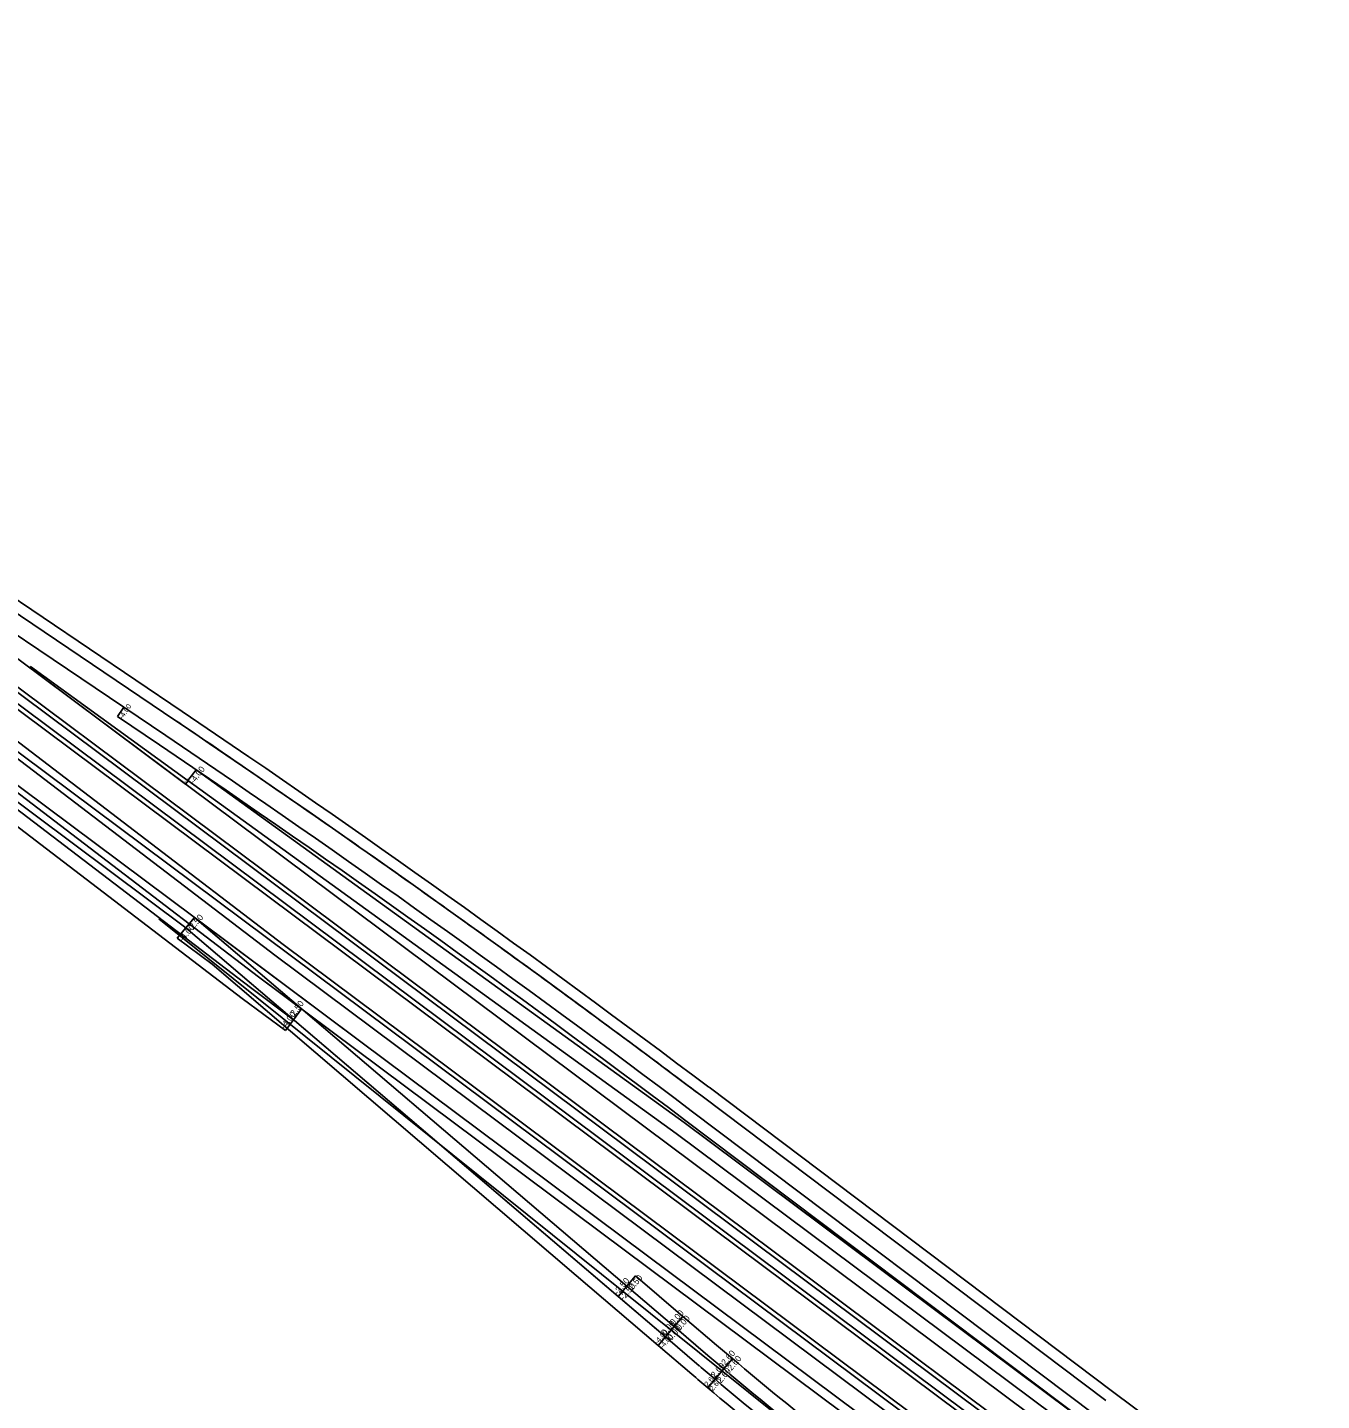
# Model space of a CAD drawing. Extents: x 2342222 to 2351711, y 366548 to 372860.
# Drawn here: x 2344214 to 2345363, y 370762 to 371981 of the extents above; entities that cross this region are included whole.
import ezdxf

# ---------------------------------------------------------------- set-up
doc = ezdxf.new("R2010")
doc.units = 0
for name, color, linetype in [('RD_PD_Final_LnLine', 7, 'Continuous'), ('RD_PD_PaveShd', 7, 'Continuous'), ('RD_PD_SuperShp_BL_EB_526', 7, 'Continuous'), ('RD_PD_SuperShp_BL_WB_526', 7, 'Continuous'), ('RD_PD_SuperShp_EB_526', 7, 'Continuous'), ('RD_PD_SuperShp_LINE-A', 7, 'Continuous'), ('RD_PD_SuperShp_REL_LINE-3', 7, 'Continuous'), ('RD_PD_SuperShp_WB_526', 7, 'Continuous')]:
    doc.layers.add(name, color=color, linetype=linetype)

msp = doc.modelspace()

# ---------------------------------------------------------------- linework, layer by layer
at = {"layer": 'RD_PD_Final_LnLine'}
msp.add_line((2344330.6, 371189.3), (2344989.7, 370660.6), dxfattribs=at)
msp.add_line((2344330.6, 371189.3), (2344989.7, 370660.6), dxfattribs=at)
at = {"layer": 'RD_PD_PaveShd'}
for p, q in [((2344136.5, 371426.7), (2345306.6, 370553.4)), ((2344363.7, 371321.8), (2344797.2, 371008.5)), ((2344797.2, 371008.5), (2345171.3, 370729.2))]:
    msp.add_line(p, q, dxfattribs=at)
at = {"layer": 'RD_PD_SuperShp_BL_EB_526'}
for p, q in [((2344441, 371166.6), (2343459.8, 371915.6)), ((2343465, 371896.5), (2344433.7, 371157)), ((2343853.9, 371599.7), (2344433.7, 371157)), ((2344419.3, 371137.9), (2343839.3, 371580.6)), ((2344419.3, 371137.9), (2343839.3, 371580.6)), ((2343832.1, 371571), (2344412.1, 371128.3)), ((2344412.1, 371128.3), (2343832.1, 371571)), ((2343824.8, 371561.5), (2344404.8, 371118.7)), ((2345290.9, 370532.3), (2344441, 371166.6)), ((2344433.7, 371157), (2345206.8, 370580.1)), ((2344433.7, 371157), (2345283.7, 370522.7)), ((2344412.1, 371128.3), (2344450.2, 371099.8)), ((2344450.2, 371099.8), (2344412.1, 371128.3)), ((2345192.4, 370560.9), (2344419.3, 371137.9)), ((2344457.4, 371109.4), (2344419.3, 371137.9)), ((2344404.8, 371118.7), (2344443, 371090.2)), ((2344450.2, 371099.8), (2344457.4, 371109.4)), ((2344443, 371090.2), (2344450.2, 371099.8))]:
    msp.add_line(p, q, dxfattribs=at)
at = {"layer": 'RD_PD_SuperShp_BL_WB_526'}
for p, q in [((2345328.2, 370582.3), (2344157.9, 371455.7)), ((2344143.6, 371436.4), (2345313.8, 370563)), ((2345236.9, 370620.4), (2344143.6, 371436.4)), ((2344136.5, 371426.7), (2345229.7, 370610.8)), ((2344216.6, 371413.3), (2344215.9, 371412.4)), ((2344215.9, 371412.4), (2344354.4, 371309)), ((2344356.7, 371312), (2344216.6, 371413.3)), ((2344354.4, 371309), (2344356.6, 371311.9)), ((2344363.7, 371321.8), (2344356.5, 371312.1)), ((2344356.5, 371312.1), (2344790.1, 370998.8)), ((2344356.6, 371311.9), (2344356.7, 371312)), ((2344797.2, 371008.5), (2344363.7, 371321.8)), ((2345171.3, 370729.2), (2344797.2, 371008.5)), ((2344790.1, 370998.8), (2345335.3, 370591.9))]:
    msp.add_line(p, q, dxfattribs=at)
at = {"layer": 'RD_PD_SuperShp_EB_526'}
for p, q in [((2345288.6, 370529.2), (2343854.1, 371599.9)), ((2344362.1, 371190.8), (2343839.8, 371580.6)), ((2343839.8, 371580.6), (2344362.1, 371190.8)), ((2343832.6, 371571), (2344354.6, 371181.4)), ((2344354.6, 371181.4), (2344362.3, 371190.5)), ((2344510.1, 371080.3), (2344362.1, 371190.8)), ((2344362.3, 371190.5), (2344362.1, 371190.8)), ((2344362.1, 371190.8), (2344362.3, 371190.5)), ((2344362.3, 371190.5), (2344510.1, 371080.3)), ((2344510.1, 371080.3), (2345274.2, 370510))]:
    msp.add_line(p, q, dxfattribs=at)
at = {"layer": 'RD_PD_SuperShp_LINE-A'}
for p, q in [((2343974.3, 371616), (2344345.7, 371365.3)), ((2344345.7, 371365.3), (2343974.3, 371616)), ((2344351.3, 371373.6), (2343979.9, 371624.3)), ((2343965.4, 371602.8), (2344336.8, 371352.1)), ((2343965.4, 371602.8), (2344336.8, 371352.1)), ((2344299.5, 371377.3), (2344293.9, 371369)), ((2344336.8, 371352.1), (2344299.5, 371377.3)), ((2344293.9, 371369), (2344331.2, 371343.8)), ((2344813.1, 371031.8), (2345171.5, 370761.7)), ((2345171.5, 370761.7), (2344813.1, 371031.8)), ((2345177.5, 370769.6), (2344819.2, 371039.8)), ((2345161.9, 370748.9), (2344803.5, 371019)), ((2344803.5, 371019), (2345161.9, 370748.9)), ((2344797.5, 371011), (2345155.9, 370740.9))]:
    msp.add_line(p, q, dxfattribs=at)
for centre, radius, start, end in [((2338191.8, 362247.8), 11010, 52.99132, 55.9825), ((2338191.8, 362247.8), 11000, 52.99132, 55.9825), ((2338191.8, 362247.8), 11000, 55.85251, 55.9825), ((2338191.8, 362247.8), 10984, 52.99132, 55.9825), ((2338191.8, 362247.8), 10984, 52.99132, 55.9825), ((2338191.8, 362247.8), 11000, 55.33164, 55.85251), ((2338191.8, 362247.8), 10974, 52.99132, 55.9825), ((2338191.8, 362247.8), 11000, 54.81077, 55.33164), ((2338191.8, 362247.8), 11000, 54.2899, 54.81077), ((2338191.8, 362247.8), 11000, 53.76902, 54.2899), ((2338191.8, 362247.8), 11000, 53.24815, 53.76902), ((2338191.8, 362247.8), 11000, 52.99132, 53.24815), ((2352034, 379865.6), 11390.7, 232.99132, 240.43629)]:
    msp.add_arc(centre, radius, start, end, dxfattribs=at)
at = {"layer": 'RD_PD_SuperShp_REL_LINE-3'}
for p, q in [((2344362.3, 371190.5), (2344354.6, 371181.4)), ((2344746.2, 370863.2), (2344362.3, 371190.5)), ((2344354.6, 371181.4), (2344346.8, 371172.3)), ((2344354.6, 371181.4), (2344738.4, 370854.1)), ((2344780.5, 370818.1), (2344354.6, 371181.4)), ((2344346.8, 371172.3), (2344377.9, 371149)), ((2344377.9, 371149), (2344701.1, 370872.7)), ((2344701.1, 370872.7), (2344774, 370810.5)), ((2344754, 370872.3), (2344746.2, 370863.2)), ((2344796.1, 370836.4), (2344754, 370872.3)), ((2344746.2, 370863.2), (2344738.4, 370854.1)), ((2344738.4, 370854.1), (2344746.2, 370863.2)), ((2344788.3, 370827.3), (2344746.2, 370863.2)), ((2344746.2, 370863.2), (2344788.3, 370827.3)), ((2344738.4, 370854.1), (2344780.5, 370818.1)), ((2344796.1, 370836.4), (2344788.3, 370827.3)), ((2344788.3, 370827.3), (2344796.1, 370836.4)), ((2344826, 370810.9), (2344796.1, 370836.4)), ((2344788.3, 370827.3), (2344780.5, 370818.1)), ((2344780.5, 370818.1), (2344788.3, 370827.3)), ((2344788.3, 370827.3), (2344818.2, 370801.7)), ((2344818.2, 370801.7), (2344788.3, 370827.3)), ((2344774, 370810.5), (2344780.5, 370818.1)), ((2344780.5, 370818.1), (2344774, 370810.5)), ((2344774, 370810.5), (2344804, 370785)), ((2344780.5, 370818.1), (2344810.5, 370792.6)), ((2344810.5, 370792.6), (2344780.5, 370818.1)), ((2344840.2, 370798.8), (2344832.4, 370789.7)), ((2344832.4, 370789.7), (2344840.2, 370798.8)), ((2344824.7, 370780.5), (2344832.4, 370789.7)), ((2344824.7, 370780.5), (2344832.4, 370789.7)), ((2344818.3, 370772.9), (2344824.7, 370780.5)), ((2344818.3, 370772.9), (2344824.7, 370780.5))]:
    msp.add_line(p, q, dxfattribs=at)
for radius, start, end in [(4000.5, 229.5396, 229.8057), (4012.5, 229.5396, 229.8057), (4012.5, 229.5396, 229.8057), (4000.5, 229.8057, 232.99), (4024.5, 229.5396, 229.8057), (4024.5, 229.5396, 229.8057), (4012.5, 229.8057, 232.99), (4012.5, 229.8057, 232.99), (4034.5, 229.5396, 229.8057), (4024.5, 229.8057, 232.99), (4024.5, 229.8057, 232.99), (4034.5, 229.8057, 232.99)]:
    msp.add_arc((2347422, 373854.7), radius, start, end, dxfattribs=at)
at = {"layer": 'RD_PD_SuperShp_WB_526'}
for p, q in [((2342239.6, 372847.3), (2345207.1, 370632.5)), ((2345214.3, 370642.1), (2342246.7, 372856.9))]:
    msp.add_line(p, q, dxfattribs=at)

# ---------------------------------------------------------------- texts
at = {"layer": 'RD_PD_SuperShp_BL_EB_526'}
for s, rotation, p in [('-2.50', 53.2637, (2344449.8, 371100.7)), ('-4.00', 53.2487, (2344442.7, 371091.1))]:
    msp.add_text(s, height=5.52, rotation=rotation, dxfattribs=at).set_placement(p)
at = {"layer": 'RD_PD_SuperShp_BL_WB_526'}
for s, height, p in [('-2.50', 0.513, (2344216.4, 371412.1)), ('-4.00', 5.52, (2344361.9, 371308.8)), ('-2.50', 1.67, (2344354.3, 371309.3))]:
    msp.add_text(s, height=height, rotation=53.2637, dxfattribs=at).set_placement(p)
at = {"layer": 'RD_PD_SuperShp_LINE-A'}
msp.add_text('-4.00', height=4.6, rotation=55.9784, dxfattribs=at).set_placement((2344298.5, 371366.3))
at = {"layer": 'RD_PD_SuperShp_REL_LINE-3'}
for s, height, rotation, p in [('-2.50', 5.52, 49.5402, (2344359.7, 371177.7)), ('-4.00', 5.53, 49.5396, (2344352.1, 371168.7)), ('2.50', 5.52, 49.5396, (2344751.3, 370859.4)), ('-2.50', 5.52, 49.5396, (2344738.1, 370855)), ('-2.50', 5.52, 49.5396, (2344743.5, 370850.3)), ('0.00', 5.52, 49.5396, (2344788, 370828.2)), ('0.00', 5.52, 49.5396, (2344793.4, 370823.5)), ('-4.00', 4.6, 49.5396, (2344773.7, 370811.3)), ('0.00', 5.52, 49.5396, (2344780.2, 370819)), ('0.00', 5.52, 49.5396, (2344785.7, 370814.4)), ('-4.00', 4.6, 49.5396, (2344778.3, 370807.4)), ('-2.60', 5.52, 49.8057, (2344832.1, 370790.6)), ('-2.60', 5.52, 49.8057, (2344837.6, 370785.9)), ('2.60', 5.52, 49.8057, (2344824.4, 370781.4)), ('2.60', 5.52, 49.8057, (2344829.9, 370776.8)), ('2.60', 4.6, 49.8057, (2344818, 370773.6)), ('2.60', 4.6, 49.8057, (2344822.6, 370769.7))]:
    msp.add_text(s, height=height, rotation=rotation, dxfattribs=at).set_placement(p)

doc.saveas('drawing.dxf')
